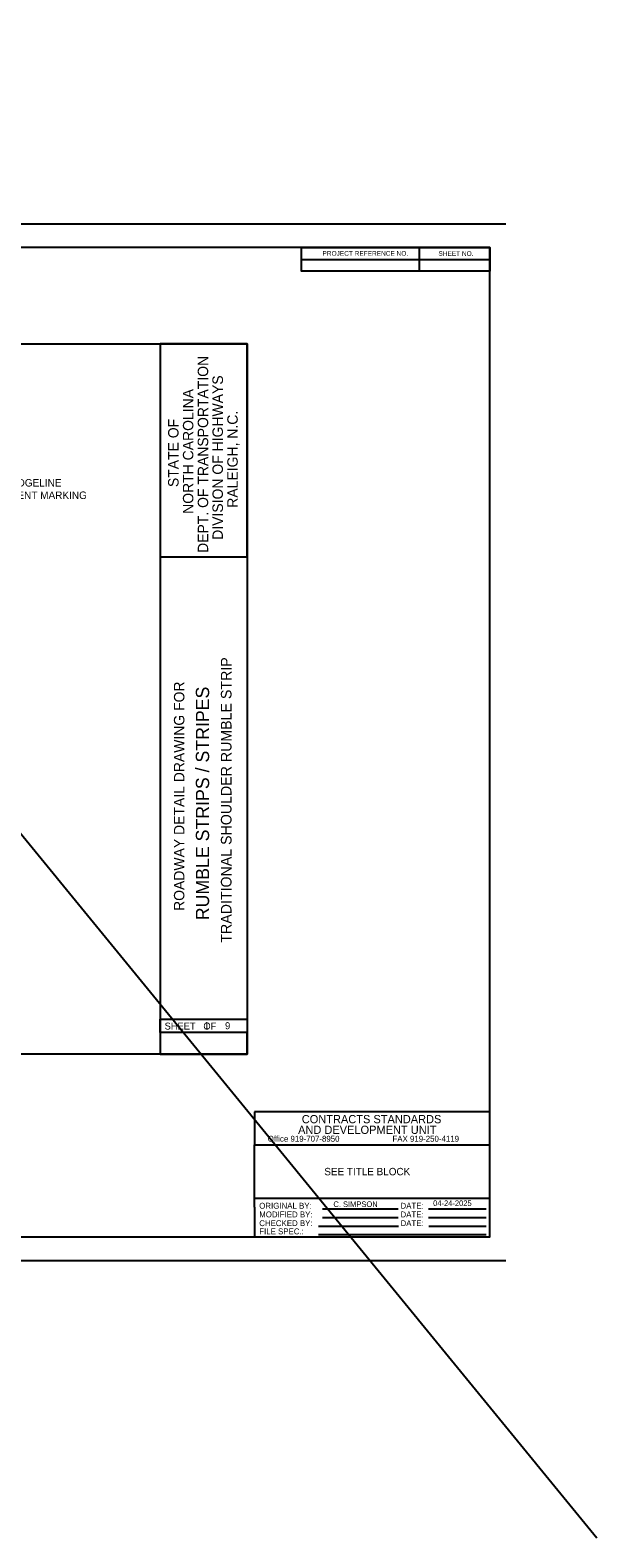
# Model space of a CAD drawing. Extents: x 1994737 to 2001433, y 527447 to 529360.
# Drawn here: x 2000714 to 2001433, y 527447 to 529360 of the extents above; entities that cross this region are included whole.
import ezdxf

# ---------------------------------------------------------------- set-up
doc = ezdxf.new("R2010")
doc.units = 0
for name, color, linetype in [('Default', 7, 'Continuous'), ('GSBWFILL', 7, 'Continuous'), ('Old_Level_1', 7, 'Continuous'), ('Old_Level_40', 7, 'Continuous'), ('Old_Level_60', 7, 'Continuous'), ('Prop Mkg Solid Yel Skip LT', 7, 'Continuous'), ('Prop Sign E Yield Sign Ahead CELL', 7, 'Continuous'), ('Prop Support Two', 7, 'Continuous')]:
    doc.layers.add(name, color=color, linetype=linetype)

msp = doc.modelspace()

# ---------------------------------------------------------------- linework, layer by layer
at = {"layer": 'Default'}
msp.add_line((1999867.3, 529360.1), (2001433.1, 527447.3), dxfattribs=at)
msp.add_lwpolyline([(1999571.4, 528962), (2000989.2, 528962), (2000989.2, 528061), (1999571.4, 528061)], close=True, dxfattribs=at)
at = {"layer": 'GSBWFILL'}
for p, q in [((2001317.7, 529114.1), (1999305.1, 529114.1)), ((1999305.1, 527799.4), (2001317.7, 527799.4))]:
    msp.add_line(p, q, dxfattribs=at)
at = {"layer": 'Old_Level_40'}
for p, q in [((2001058.3, 529069.2), (2001297.3, 529069.2)), ((2001207.7, 529084.1), (2001207.7, 529054.3))]:
    msp.add_line(p, q, dxfattribs=at)
msp.add_lwpolyline([(2001058.3, 529084.2), (2001297.3, 529084.2), (2001297.3, 529054.3), (2001058.3, 529054.3)], close=True, dxfattribs=at)
at = {"layer": 'Old_Level_60'}
for p, q in [((2001297.3, 527988), (2000998.6, 527988)), ((2000998.6, 527988), (2000998.6, 527946.1)), ((2001297.3, 527829.3), (2001297.3, 527988)), ((2000998.6, 527866.7), (2000998.6, 527946.1)), ((2000998.6, 527946.1), (2001297.3, 527946.1)), ((2001297.3, 527877.7), (2000998.6, 527877.7)), ((2000998.6, 527866.7), (2000998.6, 527829.3)), ((2001084.9, 527864.9), (2001180.8, 527864.9)), ((2001219.4, 527864.9), (2001292.4, 527864.9)), ((2001079.7, 527842.8), (2001181.2, 527842.8)), ((2001084.9, 527853.8), (2001180.8, 527853.8)), ((2001219.4, 527853.8), (2001292.4, 527853.8)), ((2001219.8, 527842.8), (2001292.4, 527842.8)), ((2000998.6, 527829.3), (2001297.3, 527829.3)), ((2001080, 527832.3), (2001292.4, 527832.3))]:
    msp.add_line(p, q, dxfattribs=at)
msp.add_lwpolyline([(2000878.8, 528691.7), (2000989.2, 528691.7), (2000989.2, 528962), (2000878.8, 528962), (2000878.8, 528061), (2000989.2, 528061), (2000989.2, 528088.6), (2000878.8, 528088.6), (2000878.8, 528105.2), (2000989.2, 528105.2)], dxfattribs=at)
at = {"layer": 'Prop Sign E Yield Sign Ahead CELL'}
msp.add_lwpolyline([(2001297.3, 529084.2), (1999504.7, 529084.2), (1999504.7, 527829.3), (2001297.3, 527829.3)], close=True, dxfattribs=at)
at = {"layer": 'Prop Support Two'}
msp.add_line((2001317.7, 529114.1), (2001317.7, 529114.1), dxfattribs=at)

# ---------------------------------------------------------------- texts
at = {"layer": 'Default'}
for s, p in [('6" EDGELINE', (2000674.4, 528781.1)), ('PAVEMENT MARKING', (2000653.3, 528765.3))]:
    msp.add_text(s, height=9.489, rotation=360, dxfattribs=at).set_placement(p)
for s, p in [('C. SIMPSON', (2001098.7, 527867)), ('04-24-2025', (2001225.3, 527868.3))]:
    msp.add_text(s, height=7.14, dxfattribs=at).set_placement(p)
at = {"layer": 'Old_Level_1'}
for s, height, p in [('TRADITIONAL SHOULDER RUMBLE STRIP', 13.461, (2000969.4, 528202.4)), ('RUMBLE STRIPS / STRIPES', 16.826, (2000941, 528230.9))]:
    msp.add_text(s, height=height, rotation=90, dxfattribs=at).set_placement(p)
msp.add_text('1      9', height=8.97, dxfattribs=at).set_placement((2000934.5, 528092.6))
at = {"layer": 'Old_Level_60'}
for s, height, rotation, p in [('DEPT. OF TRANSPORTATION', 13.245, 90, (2000939.8, 528696.9)), ('DEPT. OF TRANSPORTATION', 13.245, 90, (2000939.8, 528696.9)), ('DIVISION OF HIGHWAYS', 13.245, 90, (2000958.5, 528713.5)), ('DIVISION OF HIGHWAYS', 13.245, 90, (2000958.5, 528713.5)), ('NORTH CAROLINA', 13.245, 90, (2000921, 528746.4)), ('NORTH CAROLINA', 13.245, 90, (2000921, 528746.4)), ('RALEIGH, N.C.', 13.245, 90, (2000977.3, 528754.2)), ('RALEIGH, N.C.', 13.245, 90, (2000977.3, 528754.2)), ('STATE OF', 13.24, 90, (2000902.2, 528780.4)), ('STATE OF', 13.24, 90, (2000902.2, 528780.4)), ('ROADWAY DETAIL DRAWING FOR', 13.236, 90, (2000909.6, 528242.7)), ('SEE TITLE BLOCK', 9.406, 0.0008, (2001087.2, 527907.3))]:
    msp.add_text(s, height=height, rotation=rotation, dxfattribs=at).set_placement(p)
for s, height, p in [('SHEET   OF', 8.83, (2000884.5, 528092.2)), ('SHEET   OF', 8.83, (2000884.5, 528092.2)), ('CONTRACTS STANDARDS', 10.457, (2001058.6, 527973.3)), ('Office 919-707-8950', 7.469, (2001015.4, 527949.9)), ('AND DEVELOPMENT UNIT', 10.457, (2001053.9, 527959.8)), ('FAX 919-250-4119', 7.469, (2001173.7, 527949.9)), ('ORIGINAL BY:', 7.469, (2001004.6, 527864.9)), ('DATE:', 7.47, (2001183.9, 527864.9)), ('CHECKED BY:', 7.469, (2001004.6, 527842.8)), ('MODIFIED BY:', 7.469, (2001004.6, 527853.9)), ('DATE:', 7.47, (2001183.9, 527853.9)), ('DATE:', 7.47, (2001183.9, 527842.8)), ('FILE SPEC.:', 7.469, (2001004.6, 527832.4))]:
    msp.add_text(s, height=height, dxfattribs=at).set_placement(p)
at = {"layer": 'Prop Mkg Solid Yel Skip LT'}
for s, height, p in [('PROJECT REFERENCE NO.', 5.976, (2001084.9, 529073.9)), ('SHEET NO.', 5.98, (2001232, 529073.7))]:
    msp.add_text(s, height=height, dxfattribs=at).set_placement(p)

doc.saveas('drawing.dxf')
